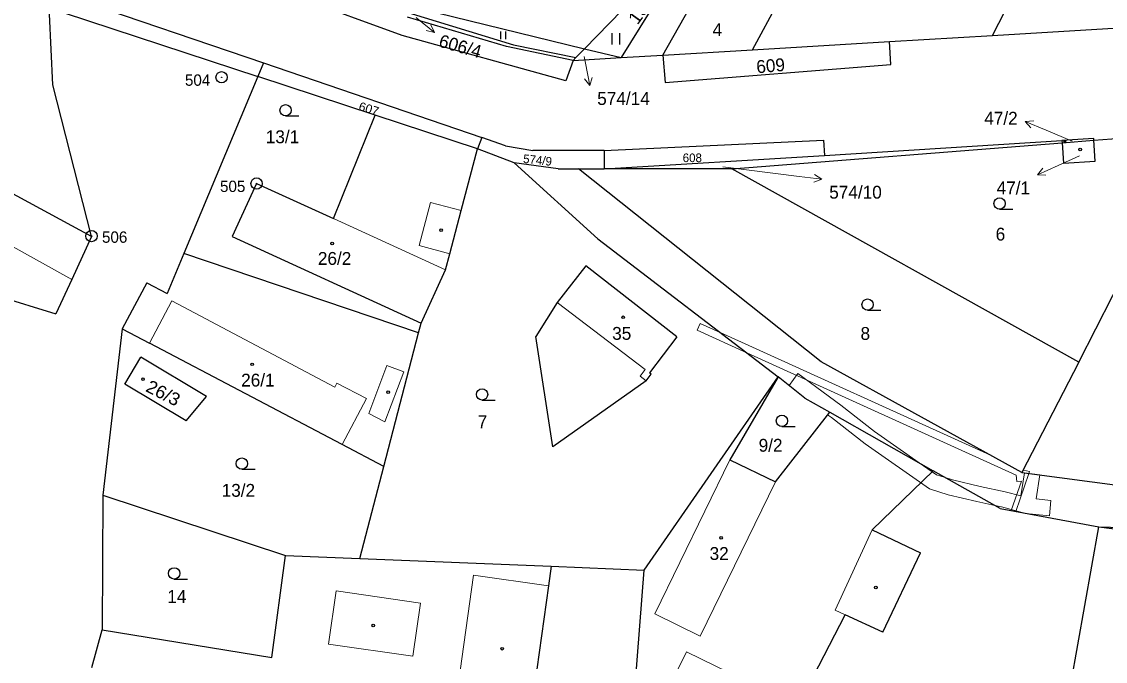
# Model space of a CAD drawing. Extents: x -664548 to -662415, y -1069720 to -1068208.
# Drawn here: x -663609.5 to -663466.2, y -1068990.4 to -1068905.8 of the extents above; entities that cross this region are included whole.
import ezdxf
from ezdxf.enums import TextEntityAlignment as Align

# ---------------------------------------------------------------- set-up
doc = ezdxf.new("R2010")
doc.units = 0
doc.header["$LTSCALE"] = 0.68
for name, color, linetype, lineweight in [('1', 7, 'Continuous', 25), ('13', 7, 'Continuous', 13), ('3', 7, 'Continuous', 25), ('4', 7, 'Continuous', 13), ('5', 7, 'Continuous', 25), ('7', 7, 'Continuous', 13), ('8', 7, 'Continuous', 25)]:
    doc.layers.add(name, color=color, linetype=linetype, lineweight=lineweight)
doc.layers.add('2', color=7, linetype='Continuous')

msp = doc.modelspace()

# ---------------------------------------------------------------- linework, layer by layer
at = {"layer": '1'}
for p, q in [((-663481.1, -1068907.57), (-663471.21, -1068888.3)), ((-663520.89, -1068895.47), (-663530.21, -1068910.52)), ((-663524.71, -1068910.19), (-663516.53, -1068895.71)), ((-663559.19, -1068907.57), (-663582.88, -1068898.95)), ((-663604.5, -1068902.02), (-663577.56, -1068911.22)), ((-663528.37, -1068902.45), (-663535.07, -1068909.34)), ((-663512.86, -1068909.48), (-663509.37, -1068903.03)), ((-663605.41, -1068914.1), (-663605.87, -1068904.77)), ((-663603.93, -1068904.61), (-663578.31, -1068913.03)), ((-663545.38, -1068909.05), (-663558.5, -1068905.16)), ((-663558.43, -1068904.54), (-663544.45, -1068908.84)), ((-663556.86, -1068904.01), (-663535.07, -1068909.34)), ((-663481.1, -1068907.57), (-663447.39, -1068905.55)), ((-663537.52, -1068913.58), (-663559.19, -1068907.57)), ((-663536.58, -1068910.89), (-663545.38, -1068909.05)), ((-663544.45, -1068908.84), (-663536.2, -1068910.5)), ((-663535.07, -1068909.34), (-663536.2, -1068910.5)), ((-663535.07, -1068909.34), (-663530.21, -1068910.52)), ((-663524.71, -1068910.19), (-663512.86, -1068909.48)), ((-663512.86, -1068909.48), (-663494.71, -1068908.39)), ((-663536.58, -1068910.89), (-663537.52, -1068913.58)), ((-663536.2, -1068910.5), (-663536.58, -1068910.89)), ((-663536.58, -1068910.89), (-663530.21, -1068910.52)), ((-663530.21, -1068910.52), (-663524.71, -1068910.19)), ((-663524.71, -1068910.19), (-663524.4, -1068913.81)), ((-663577.56, -1068911.22), (-663578.31, -1068913.03)), ((-663577.56, -1068911.22), (-663548.67, -1068921.09)), ((-663524.4, -1068913.81), (-663494.52, -1068911.43)), ((-663578.31, -1068913.03), (-663588.07, -1068936.43)), ((-663562.78, -1068918.13), (-663578.31, -1068913.03)), ((-663600.3, -1068934.16), (-663605.41, -1068914.1)), ((-663568.28, -1068931.81), (-663562.78, -1068918.13)), ((-663549.23, -1068922.59), (-663562.78, -1068918.13)), ((-663469.66, -1068950.81), (-663454.23, -1068920.37)), ((-663467.69, -1068921.44), (-663454.23, -1068920.37)), ((-663545.53, -1068922.16), (-663541.89, -1068922.78)), ((-663532.47, -1068922.78), (-663503.46, -1068921.45)), ((-663515.58, -1068925.24), (-663471.88, -1068921.77)), ((-663503.46, -1068921.45), (-663503.33, -1068923.45)), ((-663503.33, -1068923.45), (-663471.9, -1068921.48)), ((-663467.7, -1068921.21), (-663471.9, -1068921.48)), ((-663471.9, -1068921.48), (-663471.88, -1068921.77)), ((-663471.88, -1068921.77), (-663467.69, -1068921.44)), ((-663471.88, -1068921.77), (-663471.71, -1068924.47)), ((-663467.69, -1068921.44), (-663467.7, -1068921.21)), ((-663467.52, -1068924.21), (-663467.69, -1068921.44)), ((-663600.3, -1068934.16), (-663620.39, -1068923.28)), ((-663551.38, -1068930.73), (-663549.23, -1068922.59)), ((-663544.37, -1068924.45), (-663549.23, -1068922.59)), ((-663532.47, -1068922.78), (-663541.89, -1068922.78)), ((-663532.47, -1068922.78), (-663532.47, -1068925.24)), ((-663532.47, -1068925.24), (-663503.33, -1068923.45)), ((-663538.57, -1068925.24), (-663544.37, -1068924.45)), ((-663544.37, -1068924.45), (-663533.3, -1068934.46)), ((-663538.57, -1068925.24), (-663535.88, -1068925.24)), ((-663503.77, -1068950.74), (-663535.88, -1068925.24)), ((-663535.88, -1068925.24), (-663532.47, -1068925.24)), ((-663515.58, -1068925.24), (-663532.47, -1068925.24)), ((-663469.66, -1068950.81), (-663515.58, -1068925.24)), ((-663471.71, -1068924.47), (-663467.52, -1068924.21)), ((-663578.47, -1068927.15), (-663581.69, -1068934.19)), ((-663578.47, -1068927.15), (-663568.28, -1068931.81)), ((-663552.89, -1068936.45), (-663551.38, -1068930.73)), ((-663600.3, -1068934.16), (-663602.92, -1068939.87)), ((-663581.69, -1068934.19), (-663556.68, -1068945.63)), ((-663533.3, -1068934.46), (-663509.44, -1068952.74)), ((-663631.94, -1068936.09), (-663605.01, -1068944.41)), ((-663588.07, -1068936.43), (-663590.28, -1068941.72)), ((-663557.02, -1068946.93), (-663588.07, -1068936.43)), ((-663553.46, -1068938.59), (-663552.89, -1068936.45)), ((-663534.9, -1068938.03), (-663538.71, -1068942.9)), ((-663522.86, -1068947.45), (-663534.9, -1068938.03)), ((-663556.68, -1068945.63), (-663553.46, -1068938.59)), ((-663602.92, -1068939.87), (-663605.01, -1068944.41)), ((-663592.99, -1068940.29), (-663596.26, -1068946.37)), ((-663592.99, -1068940.29), (-663590.28, -1068941.72)), ((-663538.71, -1068942.9), (-663541.53, -1068947.39)), ((-663596.26, -1068946.37), (-663598.82, -1068968.37)), ((-663596.26, -1068946.37), (-663592.63, -1068948.28)), ((-663557.02, -1068946.93), (-663556.68, -1068945.63)), ((-663561.63, -1068964.61), (-663557.02, -1068946.93)), ((-663539.27, -1068962), (-663541.53, -1068947.39)), ((-663522.86, -1068947.45), (-663526.47, -1068952.21)), ((-663567.15, -1068961.7), (-663592.63, -1068948.28)), ((-663595.91, -1068953.68), (-663593.77, -1068950.12)), ((-663585.07, -1068955.35), (-663593.77, -1068950.12)), ((-663477.19, -1068965.4), (-663503.77, -1068950.74)), ((-663469.66, -1068950.81), (-663477.19, -1068965.4)), ((-663526.9, -1068953.26), (-663526.23, -1068952.39)), ((-663526.23, -1068952.39), (-663526.47, -1068952.21)), ((-663587.77, -1068958.57), (-663595.91, -1068953.68)), ((-663526.9, -1068953.26), (-663539.27, -1068962)), ((-663527.18, -1068978.29), (-663509.44, -1068952.74)), ((-663509.44, -1068952.74), (-663515.83, -1068963.69)), ((-663505.9, -1068955.56), (-663509.44, -1068952.74)), ((-663587.77, -1068958.57), (-663585.07, -1068955.35)), ((-663505.9, -1068955.56), (-663502.63, -1068957.41)), ((-663509.79, -1068966.63), (-663502.63, -1068957.41)), ((-663502.63, -1068957.41), (-663488.93, -1068965.15)), ((-663561.63, -1068964.61), (-663567.15, -1068961.7)), ((-663515.83, -1068963.69), (-663509.79, -1068966.63)), ((-663564.8, -1068976.74), (-663561.63, -1068964.61)), ((-663497.03, -1068972.97), (-663488.93, -1068965.15)), ((-663480.09, -1068970.15), (-663488.93, -1068965.15)), ((-663477.19, -1068965.4), (-663441.67, -1068970.07)), ((-663598.82, -1068968.37), (-663598.87, -1068986.19)), ((-663598.82, -1068968.37), (-663574.65, -1068976.34)), ((-663480.09, -1068970.15), (-663467, -1068972.55)), ((-663467, -1068972.55), (-663439.94, -1068976.15)), ((-663497.03, -1068972.97), (-663490.62, -1068976.02)), ((-663576.44, -1068989.85), (-663574.65, -1068976.34)), ((-663574.65, -1068976.34), (-663564.8, -1068976.74)), ((-663564.8, -1068976.74), (-663539.47, -1068977.79)), ((-663495.61, -1068986.5), (-663490.62, -1068976.02)), ((-663539.47, -1068977.79), (-663539.83, -1068980.36)), ((-663539.47, -1068977.79), (-663527.18, -1068978.29)), ((-663528.48, -1068995.25), (-663527.18, -1068978.29)), ((-663539.83, -1068980.36), (-663542.65, -1069000.26)), ((-663507.45, -1068997.46), (-663500.57, -1068984.21)), ((-663495.61, -1068986.5), (-663500.57, -1068984.21)), ((-663600.25, -1068991.18), (-663598.87, -1068986.19)), ((-663598.87, -1068986.19), (-663576.44, -1068989.85))]:
    msp.add_line(p, q, dxfattribs=at)
for points in [[(-663494.52, -1068911.43), (-663494.71, -1068908.39), (-663481.1, -1068907.57)], [(-663545.53, -1068922.16), (-663548.67, -1068921.09), (-663549.23, -1068922.59)], [(-663528.39, -1069044.47), (-663470.71, -1068993.39), (-663467, -1068972.55)], [(-663467, -1068972.55), (-663443.74, -1068973.25), (-663439.94, -1068976.15)]]:
    msp.add_lwpolyline(points, dxfattribs=at)
at = {"layer": '13'}
for points in [[(-663520.18, -1068946.57), (-663513.58, -1068949.57), (-663517.1, -1068946.87), (-663519.77, -1068945.66)], [(-663477.27, -1068966.53), (-663478.61, -1068970.42), (-663478.02, -1068970.53), (-663476.29, -1068965.52), (-663477.19, -1068965.4), (-663481.36, -1068963.1), (-663517.1, -1068946.87), (-663513.58, -1068949.57), (-663477.94, -1068965.75), (-663477.88, -1068966.57)], [(-663506.83, -1068952.31), (-663507.99, -1068953.89), (-663505.9, -1068955.56), (-663502.63, -1068957.41), (-663490.77, -1068964.11), (-663496.71, -1068959.94), (-663501.16, -1068956.48)], [(-663483.18, -1068969.24), (-663480.8, -1068969.75), (-663487.33, -1068966.06), (-663488.52, -1068965.69), (-663490.77, -1068964.11), (-663502.63, -1068957.41), (-663502.9, -1068957.75), (-663502.4, -1068958.12), (-663497.94, -1068961.59), (-663489.44, -1068967.56), (-663486.95, -1068968.33)], [(-663486.4, -1068966.34), (-663487.33, -1068966.06), (-663480.8, -1068969.75), (-663479.91, -1068969.94), (-663476.84, -1068970.75), (-663476.22, -1068970.86), (-663473.56, -1068971.12), (-663473.36, -1068969.07), (-663475.31, -1068968.88), (-663474.83, -1068965.71), (-663476.85, -1068965.44), (-663477.32, -1068968.49), (-663479.43, -1068967.94), (-663482.72, -1068967.23)], [(-663477, -1068965.08), (-663477.02, -1068965.07), (-663477.19, -1068965.4), (-663476.29, -1068965.52), (-663476.2, -1068965.26)], [(-663476.52, -1068970.83), (-663476.22, -1068970.86), (-663476.84, -1068970.75)]]:
    msp.add_lwpolyline(points, close=True, dxfattribs=at)
at = {"layer": '3'}
for p, q in [((-663546.152, -1068908.06), (-663546.152, -1068907.055)), ((-663545.482, -1068908.06), (-663545.482, -1068907.055)), ((-663531.411, -1068908.78), (-663531.411, -1068907.28)), ((-663530.41, -1068908.78), (-663530.41, -1068907.28)), ((-663574.623, -1068918.23), (-663572.873, -1068918.23)), ((-663480.153, -1068930.56), (-663478.403, -1068930.56)), ((-663497.613, -1068943.93), (-663495.863, -1068943.93)), ((-663548.633, -1068955.8), (-663546.883, -1068955.8)), ((-663508.943, -1068959.3), (-663507.193, -1068959.3)), ((-663580.413, -1068964.96), (-663578.663, -1068964.96)), ((-663589.363, -1068979.47), (-663587.613, -1068979.47))]:
    msp.add_line(p, q, dxfattribs=at)
for centre in [(-663574.6229, -1068917.4798), (-663480.1529, -1068929.8098), (-663497.6129, -1068943.1798), (-663548.6329, -1068955.0498), (-663508.9429, -1068958.5498), (-663580.4129, -1068964.2098), (-663589.3629, -1068978.7198)]:
    msp.add_circle(centre, 0.75, dxfattribs=at)
at = {"layer": '4'}
for p, q in [((-663568.28, -1068931.81), (-663553.46, -1068938.59)), ((-663602.92, -1068939.87), (-663611.07, -1068935.31)), ((-663552.89, -1068936.45), (-663556.95, -1068935.38)), ((-663589.69, -1068942.7), (-663592.63, -1068948.28)), ((-663568.11, -1068954.08), (-663589.69, -1068942.7)), ((-663563.62, -1068957.58), (-663561.21, -1068951.22)), ((-663558.97, -1068952.06), (-663561.48, -1068958.7)), ((-663558.97, -1068952.06), (-663561.21, -1068951.22)), ((-663561.48, -1068958.7), (-663563.62, -1068957.58)), ((-663525.77, -1068984.09), (-663515.83, -1068963.69)), ((-663509.79, -1068966.63), (-663519.76, -1068987.05)), ((-663501.92, -1068983.59), (-663497.03, -1068972.97)), ((-663549.74, -1068978.96), (-663552.55, -1068998.86)), ((-663549.74, -1068978.96), (-663539.83, -1068980.36)), ((-663500.57, -1068984.21), (-663501.92, -1068983.59)), ((-663525.77, -1068984.09), (-663519.76, -1068987.05)), ((-663521.58, -1068989.08), (-663523.31, -1068992.59))]:
    msp.add_line(p, q, dxfattribs=at)
for points in [[(-663551.38, -1068930.73), (-663555.44, -1068929.66), (-663556.95, -1068935.38)], [(-663538.71, -1068942.9), (-663527.03, -1068951.78), (-663527.69, -1068952.66), (-663526.9, -1068953.26)], [(-663568.11, -1068954.08), (-663567.83, -1068953.55), (-663563.93, -1068955.6), (-663567.15, -1068961.7)], [(-663557.77, -1068989.68), (-663568.95, -1068988.08), (-663567.94, -1068981.05)], [(-663557.77, -1068989.68), (-663556.76, -1068982.65), (-663567.94, -1068981.05)], [(-663521.58, -1068989.08), (-663514.06, -1068992.78), (-663515.78, -1068996.29)]]:
    msp.add_lwpolyline(points, dxfattribs=at)
at = {"layer": '5'}
for centre, radius in [((-663471.5346, -1068921.5994), 0.1172), ((-663469.4968, -1068922.6692), 0.175), ((-663554.0568, -1068933.3392), 0.175), ((-663568.4468, -1068935.0992), 0.175), ((-663529.9468, -1068944.8592), 0.175), ((-663579.0468, -1068951.0792), 0.175), ((-663593.4868, -1068953.0292), 0.175), ((-663561.0568, -1068954.7592), 0.175), ((-663517.0068, -1068974.0192), 0.175), ((-663496.5168, -1068980.5992), 0.175), ((-663563.0168, -1068985.6292), 0.175), ((-663545.9768, -1068988.6892), 0.175)]:
    msp.add_circle(centre, radius, dxfattribs=at)
at = {"layer": '7'}
for p, q in [((-663554.928, -1068907.179), (-663555.391, -1068906.159)), ((-663534.377, -1068914.206), (-663534.077, -1068913.127)), ((-663476.752, -1068918.947), (-663476.026, -1068919.8)), ((-663503.691, -1068926.596), (-663504.624, -1068925.977)), ((-663475.132, -1068926.021), (-663474.013, -1068926.071))]:
    msp.add_line(p, q, dxfattribs=at)
for points in [[(-663557.35, -1068905.23), (-663557.26, -1068905.29), (-663554.928, -1068907.179), (-663556.021, -1068906.937)], [(-663535.12, -1068910.38), (-663534.95, -1068911.26), (-663534.377, -1068914.206), (-663535.06, -1068913.318)], [(-663470.55, -1068921.57), (-663473.99, -1068920.12), (-663476.752, -1068918.947), (-663475.635, -1068918.878)], [(-663469.56, -1068923.52), (-663472.39, -1068924.8), (-663475.132, -1068926.021), (-663474.42, -1068925.156)], [(-663516.78, -1068924.97), (-663506.67, -1068926.23), (-663503.691, -1068926.596), (-663504.746, -1068926.971)]]:
    msp.add_lwpolyline(points, dxfattribs=at)
at = {"layer": '8'}
for centre, radius in [((-663583.09, -1068913.1198), 0.75), ((-663583.09, -1068913.1198), 0.03), ((-663578.45, -1068927.1698), 0.75), ((-663578.45, -1068927.1698), 0.03), ((-663600.3, -1068934.1098), 0.75), ((-663600.3, -1068934.1098), 0.03)]:
    msp.add_circle(centre, radius, dxfattribs=at)

# ---------------------------------------------------------------- texts
at = {"layer": '2'}
for s, height, rotation, width, p in [('130/5', 1.7, 54, 1.1, (-663528.066, -1068906.279)), ('607', 1.14, 343, 1.05, (-663565.043, -1068917.432)), ('26/3', 1.7, 333, 1.05, (-663593.262, -1068954.578))]:
    msp.add_text(s, height=height, rotation=rotation, dxfattribs=dict(at, width=width)).set_placement(p)
for s, height, p in [('4', 1.7, (-663518.13, -1068907.675)), ('574/14', 1.7, (-663533.39, -1068916.775)), ('13/1', 1.7, (-663577.24, -1068921.834)), ('608', 1.14, (-663522.08, -1068924.335)), ('574/10', 1.7, (-663502.69, -1068929.165)), ('6', 1.7, (-663480.67, -1068934.705)), ('26/2', 1.7, (-663570.35, -1068937.925)), ('35', 1.7, (-663531.41, -1068947.834)), ('8', 1.7, (-663498.55, -1068947.844)), ('26/1', 1.7, (-663580.5, -1068954.015)), ('7', 1.7, (-663549.2, -1068959.525)), ('9/2', 1.7, (-663512.03, -1068962.635)), ('13/2', 1.7, (-663583.08, -1068968.594)), ('32', 1.7, (-663518.52, -1068976.945)), ('14', 1.7, (-663590.28, -1068982.635))]:
    msp.add_text(s, height=height, dxfattribs=at).set_placement(p)
msp.add_text('606/4', height=1.7, rotation=344, dxfattribs=at).set_placement((-663551.7378, -1068909.8219), align=Align.CENTER)
for s, height, rotation, p in [('609', 1.7, 5, (-663512.262, -1068912.593)), ('574/9', 1.14, 354, (-663543.239, -1068924.433))]:
    msp.add_text(s, height=height, rotation=rotation, dxfattribs=at).set_placement(p)
for s, p in [('47/2', (-663477.759, -1068919.385)), ('47/1', (-663476.119, -1068928.595))]:
    msp.add_text(s, height=1.7, dxfattribs=at).set_placement(p, align=Align.RIGHT)
at = {"layer": '8'}
for s, p in [('504', (-663584.589, -1068914.237)), ('505', (-663579.949, -1068928.287)), ('506', (-663595.564, -1068935.002))]:
    msp.add_text(s, height=1.5, dxfattribs=at).set_placement(p, align=Align.RIGHT)

doc.saveas('drawing.dxf')
